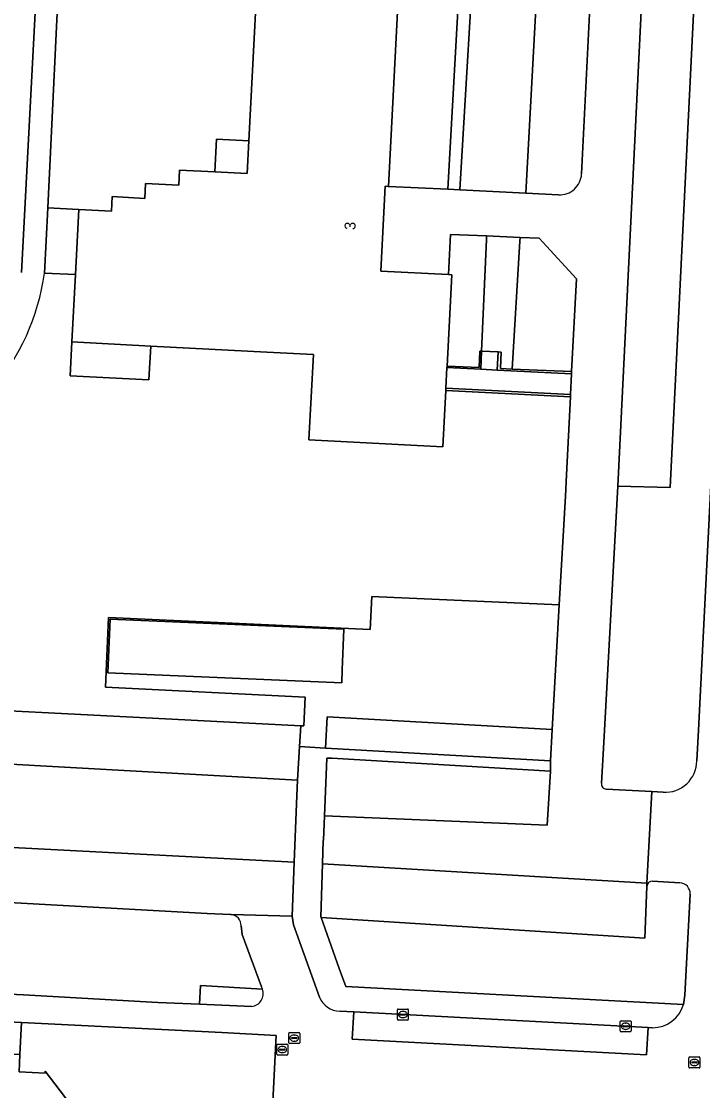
# Model space of a CAD drawing. Extents: x 161758 to 162722, y 384793 to 385405.
# Drawn here: x 161977.6 to 162039.8, y 385099.1 to 385196.7 of the extents above; entities that cross this region are included whole.
import ezdxf

# ---------------------------------------------------------------- set-up
doc = ezdxf.new("R2010")
doc.units = 0
for name, color, linetype in [('IMGEO_Erf', 7, 'Continuous'), ('IMGEO_Grasland_overig', 7, 'Continuous'), ('IMGEO_Groenvoorziening', 7, 'Continuous'), ('IMGEO_Kolk', 7, 'Continuous'), ('IMGEO_Muur', 7, 'Continuous'), ('IMGEO_Pand', 7, 'Continuous'), ('IMGEO_Pand_nummerreeks', 7, 'Continuous'), ('IMGEO_Pand_overbouw', 7, 'Continuous'), ('IMGEO_Parkeervlak_open', 7, 'Continuous'), ('IMGEO_Rijbaan_lokaal_open', 7, 'Continuous'), ('IMGEO_Rioolput', 7, 'Continuous'), ('IMGEO_Voetpad_op_trap', 7, 'Continuous'), ('IMGEO_Voetpad_open', 7, 'Continuous')]:
    doc.layers.add(name, color=color, linetype=linetype)

msp = doc.modelspace()

# ---------------------------------------------------------------- linework, layer by layer
at = {"layer": 'IMGEO_Erf'}
for points in [[(161981.177, 385204.489), (161980.001, 385179.687), (161982.832, 385179.539), (161985.809, 385179.383), (161985.878, 385180.708), (161988.855, 385180.552), (161988.926, 385181.907), (161991.961, 385181.748), (161992.034, 385183.141), (161995.237, 385182.974), (161995.393, 385185.95), (161998.339, 385185.796), (161999.484, 385207.449)], [(161999.484, 385207.449), (162000, 385207.426), (162013.693, 385206.817), (162013.411, 385200.476), (162012.078, 385200.553), (162011.09, 385181.643), (162016.495, 385181.377), (162017.991, 385208.043)], [(161977.591, 385173.789), (161979.288, 385205.662)], [(162027.687, 385162.435), (162016.32, 385163.028), (162016.05, 385157.86), (162003.831, 385158.499), (162004.238, 385166.297), (162000, 385166.518), (161989.391, 385167.072), (161989.23, 385163.978), (161982.038, 385164.352), (161982.2, 385167.448), (161982.521, 385173.588), (161979.69, 385173.736)], [(161965.164, 385156.643), (161964.692, 385152.152), (161963.948, 385134.408), (161964.359, 385134.387), (161965.449, 385129.516), (161967.88, 385129.394), (161968.143, 385134.194), (161989.567, 385133.099), (162003.081, 385132.412), (162003.361, 385132.398), (162003.491, 385135.034), (161985.277, 385135.928), (161985.553, 385142.306), (162009.423, 385141.196), (162009.571, 385144.216), (162026.662, 385143.457), (162027.233, 385153.373), (162027.321, 385155.326), (162027.687, 385162.435)], [(161917.587, 385105.411), (161977.45, 385102.402), (161977.597, 385105.328), (161906.144, 385108.941)]]:
    msp.add_lwpolyline(points, dxfattribs=at)
msp.add_arc((161959.026, 385176.578), 20.858, 287.1133, 352.1695, dxfattribs=at)
at = {"layer": 'IMGEO_Grasland_overig'}
msp.add_lwpolyline([(162020.036, 385176.787), (162020.05, 385177.123), (162016.756, 385177.266), (162016.563, 385173.593), (162016.871, 385173.577), (162016.435, 385165.238), (162019.352, 385165.111), (162019.417, 385166.612), (162019.594, 385166.604)], close=True, dxfattribs=at)
at = {"layer": 'IMGEO_Groenvoorziening'}
for points in [[(162043.143, 385206.972), (162042.032, 385207.027), (162042.094, 385208.254), (162043.204, 385208.198), (162043.484, 385213.778), (162034.554, 385205.704), (162039.307, 385205.47), (162036.811, 385154.145), (162032.024, 385154.286), (162030.75, 385130.879), (162030.52, 385127.158)], [(162019.151, 385207.404), (162017.59, 385181.323), (162023.619, 385181.027), (162024.787, 385202.4)], [(162039.217, 385129.199), (162039.383, 385132.009), (162043.143, 385206.972)], [(162030.951, 385126.619), (162035.122, 385126.398), (162036.164, 385126.343)], [(161996.732, 385115.177), (161996.684, 385115.179), (161994.549, 385115.285), (161967.145, 385116.808), (161967.414, 385121.793), (161964.337, 385121.884), (161963.7, 385120.971), (161963.322, 385114.171), (161963.48, 385112.965)], [(162034.664, 385117.75), (162034.47, 385113.006), (162004.941, 385114.912), (162006.584, 385110.265), (162007.187, 385108.606), (162038.015, 385106.967), (162038.13, 385107.817), (162038.616, 385117.042)], [(162037.678, 385118.06), (162035.191, 385118.215)], [(161997.753, 385113.342), (161997.636, 385114.136)], [(161999.498, 385108.566), (161997.753, 385113.342)], [(161965.948, 385109.098), (161966.865, 385108.373), (161968.71, 385108.279), (161977.77, 385107.843), (161990.048, 385107.161), (161993.831, 385106.994), (161993.934, 385108.703), (161999.593, 385108.362)]]:
    msp.add_lwpolyline(points, dxfattribs=at)
msp.add_lwpolyline([(162026.022, 385132.057), (162005.482, 385133.211), (162005.342, 385130.372), (162025.861, 385129.196)], close=True, dxfattribs=at)
for centre, radius, start, end in [((162036.356, 385129.198), 2.861, 266.15997, 0.02108), ((162031.035, 385127.128), 0.516, 176.67609, 260.61759), ((162035.166, 385117.713), 0.503, 87.10101, 175.74633), ((162037.665, 385117.107), 0.953, 356.07791, 89.23793), ((161996.657, 385114.199), 0.981, 356.30138, 85.64044), ((161998.564, 385108.007), 1.089, 19.03829, 30.90321)]:
    msp.add_arc(centre, radius, start, end, dxfattribs=at)
at = {"layer": 'IMGEO_Kolk'}
for p, q in [((162011.901, 385105.621), (162011.901, 385106.473)), ((162011.976, 385106.547), (162012.828, 385106.547)), ((162012.16, 385106.041), (162012.16, 385106.053)), ((162012.598, 385106.004), (162012.2, 385106.004)), ((162012.203, 385106.09), (162012.601, 385106.09)), ((162012.412, 385105.767), (162012.387, 385105.767)), ((162012.389, 385106.327), (162012.414, 385106.327)), ((162012.644, 385106.053), (162012.644, 385106.041)), ((162012.902, 385106.473), (162012.902, 385105.621)), ((162012.828, 385105.547), (162011.976, 385105.547)), ((162032.238, 385104.551), (162032.238, 385105.403)), ((162032.313, 385105.477), (162033.165, 385105.477)), ((162032.497, 385104.971), (162032.497, 385104.983)), ((162032.935, 385104.934), (162032.537, 385104.934)), ((162032.54, 385105.02), (162032.938, 385105.02)), ((162032.749, 385104.697), (162032.724, 385104.697)), ((162032.726, 385105.257), (162032.751, 385105.257)), ((162032.981, 385104.983), (162032.981, 385104.971)), ((162033.239, 385105.403), (162033.239, 385104.551)), ((162033.165, 385104.477), (162032.313, 385104.477))]:
    msp.add_line(p, q, dxfattribs=at)
for points in [[(162011.901, 385105.621), (162011.901, 385106.473)], [(162011.976, 385106.547), (162012.828, 385106.547)], [(162012.902, 385106.473), (162012.902, 385105.621)], [(162012.828, 385105.547), (162011.976, 385105.547)], [(162032.238, 385104.551), (162032.238, 385105.403)], [(162032.313, 385105.477), (162033.165, 385105.477)], [(162033.239, 385105.403), (162033.239, 385104.551)], [(162033.165, 385104.477), (162032.313, 385104.477)]]:
    msp.add_lwpolyline(points, dxfattribs=at)
for centre, radius, start, end in [((162011.978, 385106.471), 0.0765, 91.55205, 178.44795), ((162011.978, 385106.471), 0.0765, 91.55205, 178.44795), ((162011.978, 385105.623), 0.0765, 181.55205, 268.44795), ((162011.978, 385105.623), 0.0765, 181.55205, 268.44795), ((162012.2, 385106.05), 0.0403, 85.87752, 175.75265), ((162012.197, 385106.04), 0.0366, 178.93798, 274.71019), ((162012.601, 385106.047), 0.043, 264.86636, 352.45326), ((162012.605, 385106.052), 0.0386, 1.73085, 96.63898), ((162012.826, 385106.471), 0.0765, 1.55205, 88.44795), ((162012.826, 385106.471), 0.0765, 1.55205, 88.44795), ((162012.826, 385105.623), 0.0765, 271.55205, 358.44795), ((162012.826, 385105.623), 0.0765, 271.55205, 358.44795), ((162032.315, 385105.401), 0.0765, 91.55205, 178.44795), ((162032.315, 385105.401), 0.0765, 91.55205, 178.44795), ((162032.537, 385104.98), 0.0403, 85.87752, 175.75265), ((162032.534, 385104.97), 0.0366, 178.93798, 274.71019), ((162032.938, 385104.977), 0.043, 264.86636, 352.45326), ((162032.942, 385104.982), 0.0386, 1.73085, 96.63898), ((162033.163, 385105.401), 0.0765, 1.55205, 88.44795), ((162033.163, 385105.401), 0.0765, 1.55205, 88.44795), ((162032.315, 385104.553), 0.0765, 181.55205, 268.44795), ((162032.315, 385104.553), 0.0765, 181.55205, 268.44795), ((162033.163, 385104.553), 0.0765, 271.55205, 358.44795), ((162033.163, 385104.553), 0.0765, 271.55205, 358.44795)]:
    msp.add_arc(centre, radius, start, end, dxfattribs=at)
for centre, major_axis, ratio, start_param, end_param in [((162012.388, 385106.047), (-0.387, 0.002), 0.722429, 4.712389, 7.853982), ((162012.413, 385106.047), (-0.39, 0.002), 0.717154, 1.570796, 4.712389), ((162032.725, 385104.977), (-0.387, 0.002), 0.722429, 4.712389, 7.853982), ((162032.75, 385104.977), (-0.39, 0.002), 0.717154, 1.570796, 4.712389)]:
    msp.add_ellipse(centre, major_axis=major_axis, ratio=ratio, start_param=start_param, end_param=end_param, dxfattribs=at)
at = {"layer": 'IMGEO_Muur'}
for points in [[(162016.435, 385165.238), (162016.428, 385165.11), (162019.523, 385164.951), (162019.594, 385166.604), (162019.417, 385166.612), (162019.352, 385165.111)], [(162022.377, 385164.974), (162021.321, 385165.019), (162021.387, 385166.527), (162021.09, 385166.54), (162021.017, 385164.874), (162027.794, 385164.525), (162027.805, 385164.739)], [(162016.331, 385163.236), (162016.32, 385163.028), (162027.687, 385162.435), (162027.698, 385162.651)]]:
    msp.add_lwpolyline(points, close=True, dxfattribs=at)
at = {"layer": 'IMGEO_Pand'}
for points in [[(161999.484, 385207.449), (161998.339, 385185.796), (161998.182, 385182.82), (161995.237, 385182.974), (161992.034, 385183.141), (161991.961, 385181.748), (161988.926, 385181.907), (161988.855, 385180.552), (161985.878, 385180.708), (161985.809, 385179.383), (161982.832, 385179.539), (161982.521, 385173.588), (161982.2, 385167.448), (161989.391, 385167.072), (162000, 385166.518), (162004.238, 385166.297), (162003.831, 385158.499), (162016.05, 385157.86), (162016.32, 385163.028), (162016.331, 385163.236), (162016.428, 385165.11), (162016.435, 385165.238), (162016.871, 385173.577), (162016.563, 385173.593), (162010.395, 385173.916), (162010.8, 385181.659), (162011.09, 385181.643), (162012.078, 385200.553)], [(161985.24, 385093.706), (161979.765, 385100.88), (161979.762, 385100.69), (161977.382, 385100.813), (161977.45, 385102.402), (161917.587, 385105.411), (161916.871, 385091.004)]]:
    msp.add_lwpolyline(points, dxfattribs=at)
msp.add_lwpolyline([(161985.484, 385137.236), (162006.821, 385136.335), (162006.872, 385137.52), (162007.028, 385141.228), (161985.691, 385142.129)], close=True, dxfattribs=at)
at = {"layer": 'IMGEO_Pand_overbouw'}
for points in [[(161995.237, 385182.974), (161998.182, 385182.82), (161998.339, 385185.796), (161995.393, 385185.95)], [(161982.832, 385179.539), (161980.001, 385179.687), (161979.69, 385173.736), (161982.521, 385173.588)], [(161989.391, 385167.072), (161982.2, 385167.448), (161982.038, 385164.352), (161989.23, 385163.978)]]:
    msp.add_lwpolyline(points, close=True, dxfattribs=at)
at = {"layer": 'IMGEO_Parkeervlak_open'}
for points in [[(162029.851, 385205.935), (162024.917, 385206.178), (162024.892, 385205.168), (162024.787, 385202.4), (162023.619, 385181.027), (162026.615, 385180.88)], [(162028.711, 385182.779), (162029.851, 385205.935)]]:
    msp.add_lwpolyline(points, dxfattribs=at)
for points in [[(162034.554, 385205.704), (162032.024, 385154.286), (162036.811, 385154.145), (162039.307, 385205.47)], [(162028.24, 385173.2), (162025.161, 385176.565), (162024.84, 385176.916), (162023.107, 385176.991), (162023.086, 385176.655), (162022.377, 385164.974), (162027.805, 385164.739)], [(162003.081, 385132.412), (161989.567, 385133.099), (161968.143, 385134.194), (161967.88, 385129.394), (162002.797, 385127.445), (162002.968, 385130.508)], [(162025.874, 385128.279), (162005.935, 385129.442), (162005.474, 385129.453), (162005.31, 385125.674), (162005.247, 385124.191), (162025.585, 385123.322)], [(162002.49, 385119.968), (161967.414, 385121.793), (161967.145, 385116.808), (161994.549, 385115.285), (161996.684, 385115.179), (161996.732, 385115.177), (162002.303, 385115.018)], [(162034.664, 385117.75), (162034.68, 385118.052), (162005.057, 385119.793), (162004.918, 385114.977), (162004.941, 385114.912), (162034.47, 385113.006)], [(162034.777, 385104.87), (162007.915, 385106.283), (162007.783, 385103.807), (162034.646, 385102.379)]]:
    msp.add_lwpolyline(points, close=True, dxfattribs=at)
msp.add_arc((162026.715, 385182.876), 1.999, 267.14036, 357.21351, dxfattribs=at)
at = {"layer": 'IMGEO_Rijbaan_lokaal_open'}
for points in [[(162034.554, 385205.704), (162029.851, 385205.935), (162028.711, 385182.779)], [(162030.52, 385127.158), (162030.75, 385130.879), (162032.024, 385154.286), (162034.554, 385205.704)], [(162026.615, 385180.88), (162023.619, 385181.027), (162017.59, 385181.323), (162016.495, 385181.377), (162011.09, 385181.643), (162010.8, 385181.659), (162010.395, 385173.916), (162016.563, 385173.593), (162016.756, 385177.266), (162020.05, 385177.123), (162023.107, 385176.991), (162024.84, 385176.916), (162025.161, 385176.565), (162028.24, 385173.2), (162027.805, 385164.739), (162027.794, 385164.525), (162027.698, 385162.651), (162027.687, 385162.435), (162027.321, 385155.326), (162027.233, 385153.373), (162026.662, 385143.457), (162026.022, 385132.057), (162025.861, 385129.196), (162025.874, 385128.279), (162025.585, 385123.322), (162005.247, 385124.191), (162005.151, 385121.953), (162005.119, 385121.945), (162005.057, 385119.793), (162034.68, 385118.052), (162035.122, 385126.398), (162030.951, 385126.619)]]:
    msp.add_lwpolyline(points, dxfattribs=at)
msp.add_lwpolyline([(162002.719, 385126.047), (162002.797, 385127.445), (161967.88, 385129.394), (161967.414, 385121.793), (162002.49, 385119.968)], close=True, dxfattribs=at)
for centre, radius, start, end in [((162026.715, 385182.876), 1.999, 267.14036, 357.21351), ((162031.035, 385127.128), 0.516, 176.67609, 260.61759)]:
    msp.add_arc(centre, radius, start, end, dxfattribs=at)
at = {"layer": 'IMGEO_Rioolput'}
for p, q in [((162001.988, 385103.473), (162001.988, 385104.325)), ((162002.063, 385104.399), (162002.915, 385104.399)), ((162002.247, 385103.893), (162002.247, 385103.905)), ((162002.685, 385103.856), (162002.287, 385103.856)), ((162002.29, 385103.942), (162002.688, 385103.942)), ((162002.476, 385104.179), (162002.501, 385104.179)), ((162002.731, 385103.905), (162002.731, 385103.893)), ((162002.989, 385104.325), (162002.989, 385103.473)), ((162000.897, 385102.422), (162000.897, 385103.274)), ((162000.972, 385103.348), (162001.824, 385103.348)), ((162001.156, 385102.842), (162001.156, 385102.854)), ((162001.594, 385102.805), (162001.196, 385102.805)), ((162001.199, 385102.891), (162001.597, 385102.891)), ((162001.385, 385103.128), (162001.41, 385103.128)), ((162001.64, 385102.854), (162001.64, 385102.842)), ((162001.898, 385103.274), (162001.898, 385102.422)), ((162002.915, 385103.399), (162002.063, 385103.399)), ((162002.499, 385103.619), (162002.474, 385103.619)), ((162001.824, 385102.348), (162000.972, 385102.348)), ((162001.408, 385102.568), (162001.383, 385102.568)), ((162038.511, 385101.247), (162038.511, 385102.099)), ((162038.586, 385102.173), (162039.438, 385102.173)), ((162038.813, 385101.716), (162039.211, 385101.716)), ((162038.999, 385101.953), (162039.024, 385101.953)), ((162039.512, 385102.099), (162039.512, 385101.247)), ((162039.438, 385101.173), (162038.586, 385101.173)), ((162038.77, 385101.667), (162038.77, 385101.679)), ((162039.208, 385101.63), (162038.81, 385101.63)), ((162039.022, 385101.393), (162038.997, 385101.393)), ((162039.254, 385101.679), (162039.254, 385101.667))]:
    msp.add_line(p, q, dxfattribs=at)
for points in [[(162001.988, 385103.473), (162001.988, 385104.325)], [(162002.063, 385104.399), (162002.915, 385104.399)], [(162002.989, 385104.325), (162002.989, 385103.473)], [(162000.897, 385102.422), (162000.897, 385103.274)], [(162000.972, 385103.348), (162001.824, 385103.348)], [(162001.898, 385103.274), (162001.898, 385102.422)], [(162002.915, 385103.399), (162002.063, 385103.399)], [(162001.824, 385102.348), (162000.972, 385102.348)], [(162038.511, 385101.247), (162038.511, 385102.099)], [(162038.586, 385102.173), (162039.438, 385102.173)], [(162039.512, 385102.099), (162039.512, 385101.247)], [(162039.438, 385101.173), (162038.586, 385101.173)]]:
    msp.add_lwpolyline(points, dxfattribs=at)
for centre, radius, start, end in [((162002.065, 385104.323), 0.0765, 91.55205, 178.44795), ((162002.065, 385104.323), 0.0765, 91.55205, 178.44795), ((162002.287, 385103.902), 0.0403, 85.87752, 175.75265), ((162002.284, 385103.892), 0.0366, 178.93798, 274.71019), ((162002.688, 385103.899), 0.043, 264.86636, 352.45326), ((162002.692, 385103.904), 0.0386, 1.73085, 96.63898), ((162002.913, 385104.323), 0.0765, 1.55205, 88.44795), ((162002.913, 385104.323), 0.0765, 1.55205, 88.44795), ((162000.974, 385103.272), 0.0765, 91.55205, 178.44795), ((162000.974, 385103.272), 0.0765, 91.55205, 178.44795), ((162001.196, 385102.851), 0.0403, 85.87752, 175.75265), ((162001.193, 385102.841), 0.0366, 178.93798, 274.71019), ((162001.597, 385102.848), 0.043, 264.86636, 352.45326), ((162001.601, 385102.853), 0.0386, 1.73085, 96.63898), ((162001.822, 385103.272), 0.0765, 1.55205, 88.44795), ((162001.822, 385103.272), 0.0765, 1.55205, 88.44795), ((162002.065, 385103.475), 0.0765, 181.55205, 268.44795), ((162002.065, 385103.475), 0.0765, 181.55205, 268.44795), ((162002.913, 385103.475), 0.0765, 271.55205, 358.44795), ((162002.913, 385103.475), 0.0765, 271.55205, 358.44795), ((162000.974, 385102.424), 0.0765, 181.55205, 268.44795), ((162000.974, 385102.424), 0.0765, 181.55205, 268.44795), ((162001.822, 385102.424), 0.0765, 271.55205, 358.44795), ((162001.822, 385102.424), 0.0765, 271.55205, 358.44795), ((162038.588, 385102.097), 0.0765, 91.55205, 178.44795), ((162038.588, 385102.097), 0.0765, 91.55205, 178.44795), ((162038.81, 385101.676), 0.0403, 85.87752, 175.75265), ((162039.215, 385101.678), 0.0386, 1.73085, 96.63898), ((162039.436, 385102.097), 0.0765, 1.55205, 88.44795), ((162039.436, 385102.097), 0.0765, 1.55205, 88.44795), ((162038.588, 385101.249), 0.0765, 181.55205, 268.44795), ((162038.588, 385101.249), 0.0765, 181.55205, 268.44795), ((162038.807, 385101.666), 0.0366, 178.93798, 274.71019), ((162039.211, 385101.673), 0.043, 264.86636, 352.45326), ((162039.436, 385101.249), 0.0765, 271.55205, 358.44795), ((162039.436, 385101.249), 0.0765, 271.55205, 358.44795)]:
    msp.add_arc(centre, radius, start, end, dxfattribs=at)
for centre, major_axis, ratio, start_param, end_param in [((162002.475, 385103.899), (-0.387, 0.002), 0.722429, 4.712389, 7.853982), ((162002.5, 385103.899), (-0.39, 0.002), 0.717154, 1.570796, 4.712389), ((162001.384, 385102.848), (-0.387, 0.002), 0.722429, 4.712389, 7.853982), ((162001.409, 385102.848), (-0.39, 0.002), 0.717154, 1.570796, 4.712389), ((162038.998, 385101.673), (-0.387, 0.002), 0.722429, 4.712389, 7.853982), ((162039.023, 385101.673), (-0.39, 0.002), 0.717154, 1.570796, 4.712389)]:
    msp.add_ellipse(centre, major_axis=major_axis, ratio=ratio, start_param=start_param, end_param=end_param, dxfattribs=at)
at = {"layer": 'IMGEO_Voetpad_op_trap'}
msp.add_lwpolyline([(162021.09, 385166.54), (162019.594, 385166.604), (162019.523, 385164.951), (162021.017, 385164.874)], close=True, dxfattribs=at)
at = {"layer": 'IMGEO_Voetpad_open'}
for points in [[(162054.257, 385224.66), (162057.017, 385224.521), (162062.838, 385224.227), (162091.902, 385222.76), (162092.09, 385222.751), (162097.156, 385222.503), (162118.91, 385221.436), (162119.21, 385227.479), (162089.273, 385228.907), (162056.084, 385230.578), (162046.78, 385228.577), (162044.199, 385228.022), (162043.737, 385218.822), (162043.484, 385213.778), (162043.204, 385208.198), (162043.143, 385206.972), (162039.383, 385132.009), (162039.217, 385129.199)], [(162017.991, 385208.043), (162016.495, 385181.377), (162017.59, 385181.323), (162019.151, 385207.404)], [(161979.288, 385205.662), (161977.591, 385173.789)], [(161979.69, 385173.736), (161980.001, 385179.687), (161981.177, 385204.489)], [(162005.119, 385121.945), (162005.151, 385121.953), (162005.247, 385124.191), (162005.31, 385125.674), (162005.474, 385129.453), (162005.935, 385129.442), (162025.874, 385128.279), (162025.861, 385129.196), (162005.342, 385130.372), (162002.968, 385130.508), (162002.797, 385127.445), (162002.719, 385126.047), (162002.49, 385119.968), (162002.303, 385115.018), (162002.43, 385114.239), (162004.798, 385107.638)], [(162036.164, 385126.343), (162035.122, 385126.398), (162034.68, 385118.052), (162034.664, 385117.75)], [(162038.015, 385106.967), (162007.187, 385108.606), (162006.584, 385110.265), (162004.941, 385114.912), (162004.918, 385114.977), (162005.057, 385119.793), (162005.119, 385121.945)], [(162035.191, 385118.215), (162037.678, 385118.06)], [(162038.616, 385117.042), (162038.13, 385107.817), (162038.015, 385106.967)], [(162004.798, 385107.638), (162002.43, 385114.239), (162002.303, 385115.018), (161996.732, 385115.177)], [(161997.636, 385114.136), (161997.753, 385113.342), (161999.498, 385108.566)], [(161906.144, 385108.941), (161977.597, 385105.328), (161995.883, 385104.404), (162000.829, 385104.149), (162000.14, 385090.222)], [(161998.607, 385106.783), (161993.831, 385106.994), (161990.048, 385107.161), (161977.77, 385107.843), (161968.71, 385108.279), (161966.865, 385108.373), (161965.948, 385109.098)], [(161999.593, 385108.362), (161993.934, 385108.703), (161993.831, 385106.994), (161998.607, 385106.783)], [(162006.649, 385106.35), (162007.915, 385106.283), (162034.777, 385104.87), (162035.179, 385104.849)], [(162035.179, 385104.849), (162034.777, 385104.87), (162034.646, 385102.379), (162007.783, 385103.807), (162007.915, 385106.283), (162006.649, 385106.35)], [(162000.14, 385090.222), (162000.829, 385104.149), (161995.883, 385104.404), (161977.597, 385105.328), (161977.45, 385102.402), (161977.382, 385100.813), (161979.762, 385100.69), (161979.765, 385100.88), (161985.24, 385093.706), (161985.821, 385092.944), (161990.125, 385096.301), (161990.031, 385094.355), (161989.72, 385094.124), (161989.886, 385093.899)]]:
    msp.add_lwpolyline(points, dxfattribs=at)
for points in [[(161998.339, 385185.796), (161995.393, 385185.95), (161995.237, 385182.974), (161998.182, 385182.82)], [(161979.69, 385173.736), (161982.521, 385173.588), (161982.832, 385179.539), (161980.001, 385179.687)], [(162023.107, 385176.991), (162020.05, 385177.123), (162020.036, 385176.787), (162019.594, 385166.604), (162021.09, 385166.54), (162021.387, 385166.527), (162021.321, 385165.019), (162022.377, 385164.974), (162023.086, 385176.655)], [(161982.2, 385167.448), (161982.038, 385164.352), (161989.23, 385163.978), (161989.391, 385167.072)], [(162027.794, 385164.525), (162021.017, 385164.874), (162019.523, 385164.951), (162016.428, 385165.11), (162016.331, 385163.236), (162027.698, 385162.651)], [(162026.662, 385143.457), (162009.571, 385144.216), (162009.423, 385141.196), (161985.553, 385142.306), (161985.277, 385135.928), (162003.491, 385135.034), (162003.361, 385132.398), (162003.081, 385132.412), (162002.968, 385130.508), (162005.342, 385130.372), (162005.482, 385133.211), (162026.022, 385132.057)], [(161985.484, 385137.236), (161985.691, 385142.129), (162007.028, 385141.228), (162006.872, 385137.52), (162006.821, 385136.335)]]:
    msp.add_lwpolyline(points, close=True, dxfattribs=at)
for centre, radius, start, end in [((161959.026, 385176.578), 20.858, 287.1133, 352.1695), ((162036.356, 385129.198), 2.861, 266.15997, 0.02108), ((162035.166, 385117.713), 0.503, 87.10101, 175.74633), ((162037.665, 385117.107), 0.953, 356.07791, 89.23793), ((161996.657, 385114.199), 0.981, 356.30138, 85.64044), ((161998.564, 385108.007), 1.089, 19.03829, 30.90321), ((161998.475, 385107.963), 1.187, 276.3726, 19.66231), ((161998.475, 385107.963), 1.187, 276.3726, 19.66231), ((162006.691, 385108.384), 2.035, 201.52084, 268.81567), ((162006.691, 385108.384), 2.035, 201.52084, 268.81567), ((162035.198, 385107.781), 2.932, 269.62341, 343.88329), ((162035.198, 385107.781), 2.932, 269.62341, 343.88329)]:
    msp.add_arc(centre, radius, start, end, dxfattribs=at)

# ---------------------------------------------------------------- texts
at = {"layer": 'IMGEO_Pand_nummerreeks'}
msp.add_text('3', height=1, rotation=87.00364, dxfattribs=at).set_placement((162008.066, 385177.644))

doc.saveas('drawing.dxf')
